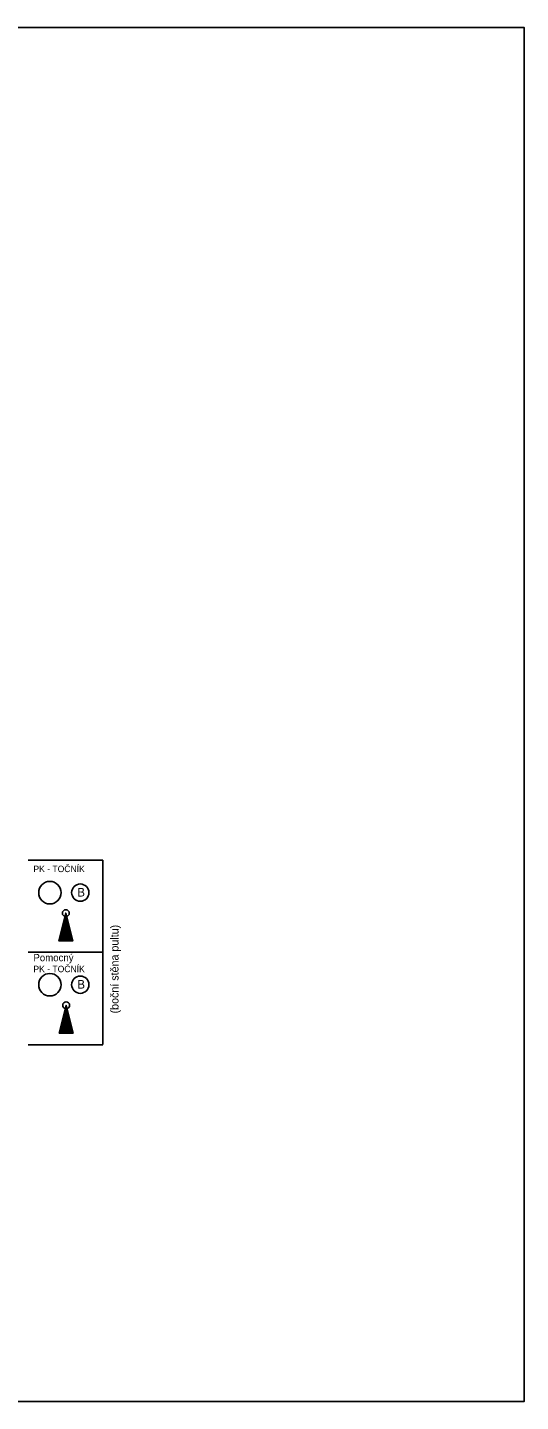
# Model space of a CAD drawing. Extents: x 0 to 840, y 0 to 297.
# Drawn here: x 522.7 to 629.2, y 0 to 297 of the extents above; entities that cross this region are included whole.
import ezdxf

# ---------------------------------------------------------------- set-up
doc = ezdxf.new("R2010")
doc.units = 0
doc.layers.add('formát tisku', color=7, linetype='Continuous')
doc.layers.add('KOLEJOVÉ_DESKY', color=7, linetype='Continuous')

# ---------------------------------------------------------------- blocks, each defined once
blk = doc.blocks.new('KONTROLKAB_P')
at = {"layer": 'KOLEJOVÉ_DESKY'}
blk.add_circle((0.004, 0.002), 0.54, dxfattribs=at)
blk.add_text('B', height=0.54, dxfattribs=at).set_placement((-0.186, -0.243))
blk = doc.blocks.new('_X16')
for p, q in [((-0.877, -1.584), (-0.255, -0.962)), ((-0.847, -1.466), (-0.273, -0.892)), ((-0.818, -1.348), (-0.291, -0.821)), ((-0.788, -1.23), (-0.308, -0.75)), ((-0.759, -1.113), (-0.326, -0.68)), ((-0.73, -0.995), (-0.344, -0.609)), ((-0.7, -0.877), (-0.361, -0.538)), ((-0.671, -0.759), (-0.379, -0.467)), ((-0.641, -0.641), (-0.397, -0.397)), ((-0.612, -0.523), (-0.414, -0.326)), ((-0.582, -0.405), (-0.432, -0.255)), ((-0.553, -0.288), (-0.45, -0.185)), ((-0.523, -0.17), (-0.467, -0.114)), ((-0.494, -0.052), (-0.485, -0.043)), ((-0.969, -2.03), (-0.185, -1.245)), ((-0.965, -1.938), (-0.202, -1.175)), ((-0.936, -1.82), (-0.22, -1.104)), ((-0.906, -1.702), (-0.238, -1.033)), ((-0.881, -2.03), (-0.167, -1.316)), ((-0.793, -2.03), (-0.149, -1.387)), ((-0.704, -2.03), (-0.132, -1.457)), ((-0.616, -2.03), (-0.114, -1.528)), ((-0.528, -2.03), (-0.096, -1.599)), ((-0.439, -2.03), (-0.079, -1.67)), ((-0.351, -2.03), (-0.061, -1.74)), ((-0.262, -2.03), (-0.043, -1.811)), ((-0.174, -2.03), (-0.026, -1.882)), ((-0.086, -2.03), (-0.008, -1.952)), ((0.003, -2.03), (0.01, -2.023))]:
    blk.add_line(p, q)
blk = doc.blocks.new('Z9')
blk.add_lwpolyline([(-0.488, -0.03), (-0.488, -0.03), (0.012, -2.03), (-0.988, -2.03)], close=True)
blk.add_lwpolyline([(-0.488, -0.03), (0.012, -2.03), (-0.988, -2.03), (-0.488, -0.03)])
for start, end in [(0, 180), (180, 0)]:
    blk.add_arc((-0.488, -0.03), 0.25, start, end)
blk.add_blockref('_X16', (0, 0))

msp = doc.modelspace()

# ---------------------------------------------------------------- linework, layer by layer
at = {"layer": 'formát tisku'}
msp.add_lwpolyline([(420, 297), (630, 297), (630, 0), (420, 0)], close=True, dxfattribs=at)
at = {"layer": 'KOLEJOVÉ_DESKY'}
for p, q in [((522.86, 117.01), (538.97, 117.01)), ((538.97, 117.01), (538.97, 77.19)), ((522.86, 97.16), (538.97, 97.16)), ((522.86, 77.13), (538.97, 77.13))]:
    msp.add_line(p, q, dxfattribs=at)
for centre in [(527.53, 109.99), (527.53, 90.1)]:
    msp.add_circle(centre, 2.43, dxfattribs=at)

# ---------------------------------------------------------------- block references
for name, p, xscale, yscale in [('KONTROLKAB_P', (534.08, 109.99), 3.459395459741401, 3.4593954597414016), ('Z9', (532.43, 105.65), 3, 3), ('KONTROLKAB_P', (534.08, 90.09), 3.459395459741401, 3.4593954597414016), ('Z9', (532.5, 85.74), 3, 3)]:
    msp.add_blockref(name, p, dxfattribs=dict(at, xscale=xscale, yscale=yscale))

# ---------------------------------------------------------------- texts
for s, height, p in [('PK - TOČNÍK', 1.3838, (523.96, 114.43)), ('Pomocný', 1.557, (523.96, 95.17)), ('PK - TOČNÍK', 1.3838, (523.96, 92.8))]:
    msp.add_text(s, height=height, dxfattribs=at).set_placement(p)
msp.add_text('(boční stěna pultu)', height=1.7297, rotation=90, dxfattribs=at).set_placement((542.35, 83.88))

doc.saveas('drawing.dxf')
